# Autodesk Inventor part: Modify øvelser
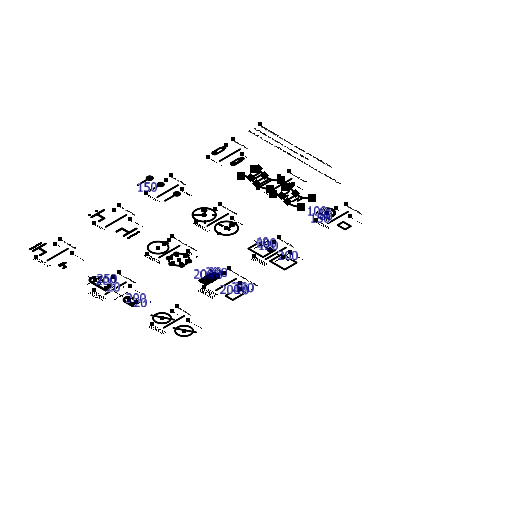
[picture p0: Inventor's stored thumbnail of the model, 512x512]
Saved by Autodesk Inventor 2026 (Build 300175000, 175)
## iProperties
Created: 2013-10
Part Number: Modify øvelser
Material: Generic
Document SubType Name: Modeling
Designer: Cadskolen
Density: 1 g/cm^3
Appearance: Default
Author: Cadskolen
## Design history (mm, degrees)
sketch "Sketch1"
  geometry: L1 (672.197, 553.166)-(672.197, 267.808); L2 (1373.06, 553.166)-(1373.06, 267.808); L3 (817.942, 330.084)-(817.942, 436.121); L4 (772.667, 436.121)-(772.667, 330.084); L5 (808.77, 317.542)-(808.77, 466.304); L6 (817.942, 436.121)-(772.667, 436.121); L7 (803.621, 448.667)-(797.585, 448.667); L8 (786.988, 448.667)-(793.025, 448.667); L9 (797.585, 448.667)-(797.585, 454.704); L10 (803.621, 454.704)-(803.621, 448.667); L11 (793.025, 448.667)-(793.025, 454.704); L12 (793.025, 454.704)-(786.988, 454.704); L13 (786.988, 454.704)-(786.988, 448.667); L14 (782.598, 466.304)-(782.598, 410.487); L15 (808.77, 466.304)-(782.598, 466.304); L16 (797.585, 454.704)-(803.621, 454.704); L17 (772.667, 330.084)-(817.942, 330.084); L18 (520.557, 436.121)-(520.557, 330.084); L19 (565.832, 330.084)-(565.832, 436.121); L20 (556.66, 436.121)-(556.66, 466.304); L21 (530.488, 466.304)-(530.488, 436.121); L22 (534.878, 454.704)-(534.878, 448.667); L23 (534.878, 448.667)-(540.915, 448.667); L24 (540.915, 454.704)-(534.878, 454.704); L25 (545.475, 448.667)-(545.475, 454.704); L26 (551.511, 448.667)-(545.475, 448.667); L27 (565.832, 436.121)-(520.557, 436.121); L28 (545.475, 454.704)-(551.511, 454.704); L29 (551.511, 454.704)-(551.511, 448.667); L30 (556.66, 466.304)-(530.488, 466.304); L31 (540.915, 448.667)-(540.915, 454.704); L32 (1508.15, 283.842)-(1508.15, 378.318); L33 (1544.627, 283.842)-(1544.627, 334.796); L34 (1595.133, 283.842)-(1595.133, 352.721); L35 (1647.744, 289.454)-(1647.744, 370.826); L36 (1675.803, 330.14)-(1675.803, 393.963); L37 (2147.529, 553.166)-(2147.529, 267.808); L38 (2060.08, 329.146)-(1980.08, 329.146); L39 (1980.08, 329.146)-(1980.08, 384.146); L40 (1980.08, 384.146)-(2060.08, 384.146); L41 (2060.08, 384.146)-(2060.08, 329.146); L42 (1969.08, 395.146)-(1969.08, 318.146); L43 (1969.08, 318.146)-(2071.08, 318.146); L44 (2071.08, 318.146)-(2071.08, 395.146); L45 (2071.08, 395.146)-(1969.08, 395.146); L46 (2095.08, 394.146)-(2095.08, 294.146); L47 (2095.08, 294.146)-(1945.08, 294.146); L48 (1945.08, 294.146)-(1945.08, 394.146); L49 (1957.08, 394.146)-(1957.08, 306.146); L50 (1957.08, 306.146)-(2083.08, 306.146); L51 (2083.08, 306.146)-(2083.08, 394.146); L52 (2235.196, 395.146)-(2235.196, 318.146); L53 (2337.196, 395.146)-(2235.196, 395.146); L54 (2337.196, 318.146)-(2337.196, 395.146); L55 (2235.196, 318.146)-(2337.196, 318.146); L56 (672.197, -297.526)-(672.197, -582.884); L57 (396.02, -439.898)-(396.02, -575.359); L58 (374.807, -388.685)-(417.234, -431.111); L59 (417.234, -388.685)-(374.807, -431.111); L60 (546.02, -439.898)-(546.02, -575.359); L61 (524.807, -388.685)-(567.234, -431.111); L62 (567.234, -388.685)-(524.807, -431.111); L63 (768.164, -439.898)-(768.164, -575.359); L64 (746.951, -388.685)-(789.377, -431.111)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; C1 r 112.734 at (1201.603, -471.521); C2 r 23.301 at (1147.293, -417.211); C3 r 112.734 at (1512.095, -477.255); C4 r 23.301 at (1512.095, -400.448); C5 r 21.824 at (2063.785, -436.894); C6 r 21.824 at (2239.449, -436.894); C7 r 5 at (1963.785, -1103.565); C8 r 5 at (1983.785, -1103.565); C9 r 5 at (2003.785, -1103.565); C10 r 5 at (2023.785, -1103.565); C11 r 5 at (1963.785, -1123.565); C12 r 5 at (1983.785, -1123.565); C13 r 5 at (2003.785, -1123.565); C14 r 5 at (2023.785, -1123.565); C15 r 5 at (1963.785, -1143.565); C16 r 5 at (1983.785, -1143.565); C17 r 5 at (2003.785, -1143.565); C18 r 5 at (2023.785, -1143.565); C19 r 5 at (1963.785, -1163.565); C20 r 5 at (1983.785, -1163.565); C21 r 5 at (2003.785, -1163.565); C22 r 5 at (2023.785, -1163.565); C23 r 5 at (1963.785, -1183.565); C24 r 5 at (1983.785, -1183.565); C25 r 5 at (2003.785, -1183.565); C26 r 5 at (2023.785, -1183.565); C27 r 5 at (1963.785, -1203.565); C28 r 5 at (1983.785, -1203.565); C29 r 5 at (2003.785, -1203.565); C30 r 5 at (2023.785, -1203.565); C31 r 5 at (1963.785, -1223.565); C32 r 5 at (1983.785, -1223.565); C33 r 5 at (2003.785, -1223.565); C34 r 5 at (2023.785, -1223.565); C35 r 5 at (1963.785, -1243.565); C36 r 5 at (1983.785, -1243.565); C37 r 5 at (2003.785, -1243.565); C38 r 5 at (2023.785, -1243.565); C39 r 5 at (1963.785, -1263.565); C40 r 5 at (1983.785, -1263.565); C41 r 5 at (2003.785, -1263.565); C42 r 5 at (2023.785, -1263.565); C43 r 5 at (2324.288, -1103.565); C44 r 86.32 at (2438.311, -1981.711); A1 r 22.638 centre (543.195, 330.084) between (520.557, 330.084) and (565.832, 330.084); A2 r 75 centre (2020.08, 394.146) between (2095.08, 394.146) and (1945.08, 394.146); A3 r 63 centre (2020.08, 394.146) between (2083.08, 394.146) and (1957.08, 394.146); A4 r 30 centre (396.02, -409.898) between (396.02, -439.898) and (374.807, -388.685); A5 r 30 centre (546.02, -409.898) between (546.02, -439.898) and (524.807, -388.685); A6 r 30 centre (768.164, -409.898) between (768.164, -439.898) and (746.951, -388.685); A7 r 100.402 centre (1275.154, -1173.633) between (1275.154, -1073.23) and (1254.153, -1075.451); A8 r 17.45 centre (1275.154, -1073.23) between (1290.267, -1064.507) and (1260.04, -1064.507); A9 r 22.559 centre (1275.154, -1073.23) between (1296.356, -1065.525) and (1253.951, -1065.525); A10 r 110.167 centre (1275.154, -1173.633) between (1296.356, -1065.525) and (1290.267, -1064.507); A11 r 110.167 centre (1275.154, -1173.633) between (1260.04, -1064.507) and (1253.951, -1065.525); A12 r 25.941 centre (1275.154, -1090.68) between (1296.154, -1075.451) and (1254.153, -1075.451); A13 r 100.402 centre (1559.731, -1173.633) between (1559.731, -1073.23) and (1538.73, -1075.451); A14 r 25.941 centre (1559.731, -1090.68) between (1580.732, -1075.451) and (1538.73, -1075.451); A15 r 22.559 centre (1559.731, -1073.23) between (1580.934, -1065.525) and (1538.529, -1065.525); A16 r 17.45 centre (1559.731, -1073.23) between (1574.844, -1064.507) and (1544.618, -1064.507); A17 r 110.167 centre (1559.731, -1173.633) between (1544.618, -1064.507) and (1538.529, -1065.525); A18 r 110.167 centre (1559.731, -1173.633) between (1580.934, -1065.525) and (1574.844, -1064.507); A19 r 110.167 centre (1559.731, -1173.633) between (1476.709, -1101.217) and (1472.782, -1105.982); A20 r 17.45 centre (1472.78, -1123.432) between (1472.782, -1105.982) and (1457.669, -1132.158); A21 r 110.167 centre (1559.731, -1173.633) between (1457.669, -1132.158) and (1455.506, -1137.941); A22 r 22.559 centre (1472.78, -1123.432) between (1476.709, -1101.217) and (1455.506, -1137.941); A23 r 25.941 centre (1487.892, -1132.157) between (1485.204, -1106.355) and (1464.203, -1142.729); A24 r 110.167 centre (1559.731, -1173.633) between (1455.506, -1209.325) and (1457.669, -1215.107); A25 r 17.45 centre (1472.78, -1223.834) between (1457.669, -1215.107) and (1472.782, -1241.284); A26 r 110.167 centre (1559.731, -1173.633) between (1472.782, -1241.284) and (1476.709, -1246.049); A27 r 22.559 centre (1472.78, -1223.834) between (1455.506, -1209.325) and (1476.709, -1246.049); A28 r 25.941 centre (1487.892, -1215.109) between (1464.203, -1204.536) and (1485.204, -1240.911); A29 r 110.167 centre (1559.731, -1173.633) between (1538.529, -1281.74) and (1544.618, -1282.758); A30 r 17.45 centre (1559.731, -1274.035) between (1544.618, -1282.758) and (1574.844, -1282.758); A31 r 110.167 centre (1559.731, -1173.633) between (1574.844, -1282.758) and (1580.934, -1281.74); A32 r 22.559 centre (1559.731, -1274.035) between (1538.529, -1281.74) and (1580.934, -1281.74); A33 r 25.941 centre (1559.731, -1256.585) between (1538.73, -1271.814) and (1580.732, -1271.814); A34 r 110.167 centre (1559.731, -1173.633) between (1642.754, -1246.049) and (1646.68, -1241.284); A35 r 17.45 centre (1646.682, -1223.834) between (1646.68, -1241.284) and (1661.793, -1215.107); A36 r 110.167 centre (1559.731, -1173.633) between (1661.793, -1215.107) and (1663.957, -1209.325); A37 r 22.559 centre (1646.682, -1223.834) between (1642.754, -1246.049) and (1663.957, -1209.325); A38 r 25.941 centre (1631.57, -1215.109) between (1634.259, -1240.911) and (1655.26, -1204.536); A39 r 110.167 centre (1559.731, -1173.633) between (1663.957, -1137.941) and (1661.793, -1132.158); A40 r 17.45 centre (1646.682, -1123.432) between (1661.793, -1132.158) and (1646.68, -1105.982); A41 r 110.167 centre (1559.731, -1173.633) between (1646.68, -1105.982) and (1642.754, -1101.217); A42 r 22.559 centre (1646.682, -1123.432) between (1663.957, -1137.941) and (1642.754, -1101.217); A43 r 25.941 centre (1631.57, -1132.157) between (1655.26, -1142.729) and (1634.259, -1106.355); A44 r 40.712 centre (1225.512, -1992.056) between (1225.512, -1951.344) and (1225.512, -2032.768); A45 r 50 centre (1225.512, -1992.056) between (1225.512, -1942.056) and (1225.512, -2042.056); A46 r 20 centre (1396.224, -1971.344) between (1416.224, -1971.344) and (1396.224, -1951.344); A47 r 20 centre (1396.224, -2012.768) between (1396.224, -2032.768) and (1416.224, -2012.768); A48 r 40.712 centre (1691.19, -1992.415) between (1691.19, -1951.703) and (1691.19, -2033.127); A49 r 49.641 centre (1691.19, -1992.415) between (1691.19, -1942.774) and (1691.19, -2042.056); A50 r 20 centre (1764.293, -1971.703) between (1784.293, -1971.703) and (1764.293, -1951.703); A51 r 20 centre (1764.293, -2013.127) between (1764.293, -2033.127) and (1784.293, -2013.127); A52 r 86.32 centre (2137.066, -1981.711) between (2055.002, -2008.481) and (2207.6, -1931.95); A53 r 86.32 centre (2137.066, -1981.711) between (2207.6, -1931.95) and (2055.002, -2008.481); 73 further points
  constraints: 304 end point, 117 point on circle, 97 centre point, 43 parallel, 38 perpendicular, 14 coincident, 13 horizontal alignment, 11 tangent, 10 point on line, 6 horizontal, 3 collinear, 3 equal length, 2 equal radius, 1 midpoint, 90 other
  dimensions: "d181" = 55 distance between parallel lines of L40 L38; "d182" = 80 distance between parallel lines of L41 L39; "d189" = 150 distance of L46.end L47.end; "d190" = 100 distance of L47.end L48.end; "d194" = 150 distance between parallel lines of L57 L60; "d197" = 200 distance of L72.start L72.end; "d199" = 200 distance of L78.end L76.start; "d202" = 40 distance from line of L75 point (1943.785, -436.894); "d203" = 120 distance of C5.centre point (1943.785, -436.894); "d210" = 100 distance of L103.start L103.end; "d211" = 200 distance of L105.end L103.start; "d212" = 10 diameter of C7; "d213" = 20 distance from line of L106 C7.centre; "d214" = 20 distance from line of L103 C7.centre; "d221" = 100 distance of L107.start L107.end; "d222" = 200 distance of L108.start L107.start; "d223" = 10 diameter of C43; "d224" = 20 distance from line of L108 C43.centre; "d225" = 20 distance from line of L107 C43.centre; "d226" = 20 radius of A46; "d227" = 250 dimension on A45 L137; "d228" = 20 radius of A50; "d230" = 200 distance from line of point (1225.512, -1992.056) L137; "d231" = 200 distance from line of point (1593.222, -1992.415) L144
